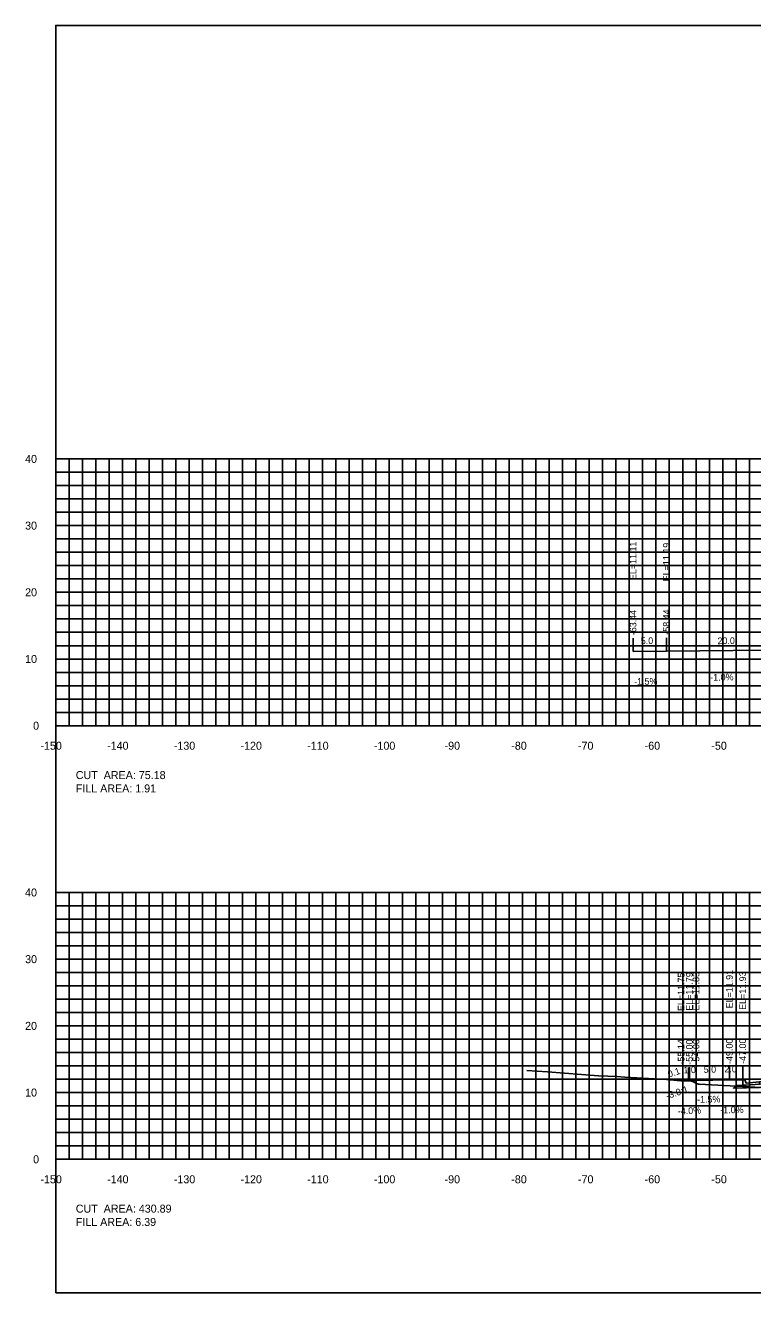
# Model space of a CAD drawing. Extents: x 1797682 to 1802785, y 249453 to 250269.
# Drawn here: x 1802476.4 to 1802585.5, y 250079.4 to 250269.4 of the extents above; entities that cross this region are included whole.
import ezdxf

# ---------------------------------------------------------------- set-up
doc = ezdxf.new("R2010")
doc.units = 0
for name, color, linetype in [('10', 7, 'Continuous'), ('3', 7, 'Continuous'), ('31', 7, 'Continuous'), ('4', 7, 'Continuous'), ('60', 7, 'Continuous'), ('ANNO-TXT', 7, 'Continuous'), ('BASE', 7, 'Continuous'), ('CL-CNST', 7, 'Continuous'), ('Level 62', 7, 'Continuous'), ('M-ROADS', 7, 'Continuous')]:
    doc.layers.add(name, color=color, linetype=linetype)

msp = doc.modelspace()

# ---------------------------------------------------------------- linework, layer by layer
for p, q in [((1802567.56, 250175.54), (1802567.56, 250177.54)), ((1802572.56, 250175.62), (1802572.56, 250177.62)), ((1802575.86, 250111.18), (1802575.86, 250113.18)), ((1802576, 250111.22), (1802576, 250113.22)), ((1802577, 250111.26), (1802577, 250113.26)), ((1802582, 250111.34), (1802582, 250113.34)), ((1802584, 250111.36), (1802584, 250113.36))]:
    msp.add_line(p, q)
for points in [[(1802481, 250079.43), (1802781, 250079.43), (1802781, 250269.43), (1802481, 250269.43)], [(1802586.5, 250111.02), (1802584.5, 250110.86), (1802584.33, 250111.36), (1802584, 250111.36), (1802584, 250110.52), (1802584.5, 250110.52), (1802586.5, 250110.68)]]:
    msp.add_lwpolyline(points, close=True)
at = {"layer": '60'}
for p, q in [((1802480.94, 250204.43), (1802481, 250204.43)), ((1802481, 250164.43), (1802481, 250204.43)), ((1802480.94, 250194.43), (1802481, 250194.43)), ((1802480.94, 250184.43), (1802481, 250184.43)), ((1802480.94, 250174.43), (1802481, 250174.43)), ((1802480.94, 250164.43), (1802481, 250164.43)), ((1802481, 250164.43), (1802781, 250164.43)), ((1802481, 250164.37), (1802481, 250164.43)), ((1802491, 250164.37), (1802491, 250164.43)), ((1802501, 250164.37), (1802501, 250164.43)), ((1802511, 250164.37), (1802511, 250164.43)), ((1802521, 250164.37), (1802521, 250164.43)), ((1802531, 250164.37), (1802531, 250164.43)), ((1802541, 250164.37), (1802541, 250164.43)), ((1802551, 250164.37), (1802551, 250164.43)), ((1802561, 250164.37), (1802561, 250164.43)), ((1802571, 250164.37), (1802571, 250164.43)), ((1802581, 250164.37), (1802581, 250164.43)), ((1802480.94, 250139.43), (1802481, 250139.43)), ((1802481, 250099.43), (1802481, 250139.43)), ((1802480.94, 250129.43), (1802481, 250129.43)), ((1802480.94, 250119.43), (1802481, 250119.43)), ((1802480.94, 250109.43), (1802481, 250109.43)), ((1802480.94, 250099.43), (1802481, 250099.43)), ((1802481, 250099.43), (1802781, 250099.43)), ((1802481, 250099.37), (1802481, 250099.43)), ((1802491, 250099.37), (1802491, 250099.43)), ((1802501, 250099.37), (1802501, 250099.43)), ((1802511, 250099.37), (1802511, 250099.43)), ((1802521, 250099.37), (1802521, 250099.43)), ((1802531, 250099.37), (1802531, 250099.43)), ((1802541, 250099.37), (1802541, 250099.43)), ((1802551, 250099.37), (1802551, 250099.43)), ((1802561, 250099.37), (1802561, 250099.43)), ((1802571, 250099.37), (1802571, 250099.43)), ((1802581, 250099.37), (1802581, 250099.43))]:
    msp.add_line(p, q, dxfattribs=at)
at = {"layer": 'BASE'}
msp.add_lwpolyline([(1802672.63, 250110.24), (1802676.53, 250110.16), (1802676.13, 250110.56), (1802675.13, 250110.58), (1802674.63, 250110.58), (1802672.63, 250110.74), (1802672.63, 250110.74), (1802631, 250111.66), (1802586.5, 250110.68), (1802586.5, 250110.68), (1802584.5, 250110.52), (1802584, 250110.52), (1802583, 250110.5), (1802582.6, 250110.09), (1802586.5, 250110.18), (1802631, 250111.16)], close=True, dxfattribs=at)
at = {"layer": 'CL-CNST'}
for points in [[(1802567.56, 250175.54), (1802572.56, 250175.62), (1802592.56, 250175.82), (1802592.89, 250175.82), (1802593.06, 250175.32), (1802595.06, 250175.48), (1802631, 250176.27), (1802640.34, 250176.06), (1802642.34, 250175.9), (1802642.51, 250176.4), (1802642.84, 250176.4), (1802672.7, 250176.7)], [(1802575.86, 250111.18), (1802576, 250111.22), (1802577, 250111.26), (1802582, 250111.34), (1802584, 250111.36), (1802584.33, 250111.36), (1802584.5, 250110.86), (1802586.5, 250111.02), (1802631, 250112), (1802672.63, 250111.08), (1802674.63, 250110.92), (1802674.8, 250111.42), (1802675.13, 250111.42), (1802689.23, 250111.56)]]:
    msp.add_lwpolyline(points, dxfattribs=at)
at = {"layer": 'Level 62'}
for p, q in [((1802481, 250204.43), (1802781, 250204.43)), ((1802481, 250164.43), (1802481, 250204.43)), ((1802483, 250164.43), (1802483, 250204.43)), ((1802485, 250164.43), (1802485, 250204.43)), ((1802487, 250164.43), (1802487, 250204.43)), ((1802489, 250164.43), (1802489, 250204.43)), ((1802491, 250164.43), (1802491, 250204.43)), ((1802493, 250164.43), (1802493, 250204.43)), ((1802495, 250164.43), (1802495, 250204.43)), ((1802497, 250164.43), (1802497, 250204.43)), ((1802499, 250164.43), (1802499, 250204.43)), ((1802501, 250164.43), (1802501, 250204.43)), ((1802503, 250164.43), (1802503, 250204.43)), ((1802505, 250164.43), (1802505, 250204.43)), ((1802507, 250164.43), (1802507, 250204.43)), ((1802509, 250164.43), (1802509, 250204.43)), ((1802511, 250164.43), (1802511, 250204.43)), ((1802513, 250164.43), (1802513, 250204.43)), ((1802515, 250164.43), (1802515, 250204.43)), ((1802517, 250164.43), (1802517, 250204.43)), ((1802519, 250164.43), (1802519, 250204.43)), ((1802521, 250164.43), (1802521, 250204.43)), ((1802523, 250164.43), (1802523, 250204.43)), ((1802525, 250164.43), (1802525, 250204.43)), ((1802527, 250164.43), (1802527, 250204.43)), ((1802529, 250164.43), (1802529, 250204.43)), ((1802531, 250164.43), (1802531, 250204.43)), ((1802533, 250164.43), (1802533, 250204.43)), ((1802535, 250164.43), (1802535, 250204.43)), ((1802537, 250164.43), (1802537, 250204.43)), ((1802539, 250164.43), (1802539, 250204.43)), ((1802541, 250164.43), (1802541, 250204.43)), ((1802543, 250164.43), (1802543, 250204.43)), ((1802545, 250164.43), (1802545, 250204.43)), ((1802547, 250164.43), (1802547, 250204.43)), ((1802549, 250164.43), (1802549, 250204.43)), ((1802551, 250164.43), (1802551, 250204.43)), ((1802553, 250164.43), (1802553, 250204.43)), ((1802555, 250164.43), (1802555, 250204.43)), ((1802557, 250164.43), (1802557, 250204.43)), ((1802559, 250164.43), (1802559, 250204.43)), ((1802561, 250164.43), (1802561, 250204.43)), ((1802563, 250164.43), (1802563, 250204.43)), ((1802565, 250164.43), (1802565, 250204.43)), ((1802567, 250164.43), (1802567, 250204.43)), ((1802569, 250164.43), (1802569, 250204.43)), ((1802571, 250164.43), (1802571, 250204.43)), ((1802573, 250164.43), (1802573, 250204.43)), ((1802575, 250164.43), (1802575, 250204.43)), ((1802577, 250164.43), (1802577, 250204.43)), ((1802579, 250164.43), (1802579, 250204.43)), ((1802581, 250164.43), (1802581, 250204.43)), ((1802583, 250164.43), (1802583, 250204.43)), ((1802585, 250164.43), (1802585, 250204.43)), ((1802481, 250202.43), (1802781, 250202.43)), ((1802481, 250200.43), (1802781, 250200.43)), ((1802481, 250198.43), (1802781, 250198.43)), ((1802481, 250196.43), (1802781, 250196.43)), ((1802481, 250194.43), (1802781, 250194.43)), ((1802481, 250192.43), (1802781, 250192.43)), ((1802481, 250190.43), (1802781, 250190.43)), ((1802481, 250188.43), (1802781, 250188.43)), ((1802481, 250186.43), (1802781, 250186.43)), ((1802481, 250184.43), (1802781, 250184.43)), ((1802481, 250182.43), (1802781, 250182.43)), ((1802481, 250180.43), (1802781, 250180.43)), ((1802481, 250178.43), (1802781, 250178.43)), ((1802481, 250176.43), (1802781, 250176.43)), ((1802481, 250174.43), (1802781, 250174.43)), ((1802481, 250172.43), (1802781, 250172.43)), ((1802481, 250170.43), (1802781, 250170.43)), ((1802481, 250168.43), (1802781, 250168.43)), ((1802481, 250166.43), (1802781, 250166.43)), ((1802481, 250164.43), (1802781, 250164.43)), ((1802481, 250139.43), (1802781, 250139.43)), ((1802481, 250099.43), (1802481, 250139.43)), ((1802483, 250099.43), (1802483, 250139.43)), ((1802485, 250099.43), (1802485, 250139.43)), ((1802487, 250099.43), (1802487, 250139.43)), ((1802489, 250099.43), (1802489, 250139.43)), ((1802491, 250099.43), (1802491, 250139.43)), ((1802493, 250099.43), (1802493, 250139.43)), ((1802495, 250099.43), (1802495, 250139.43)), ((1802497, 250099.43), (1802497, 250139.43)), ((1802499, 250099.43), (1802499, 250139.43)), ((1802501, 250099.43), (1802501, 250139.43)), ((1802503, 250099.43), (1802503, 250139.43)), ((1802505, 250099.43), (1802505, 250139.43)), ((1802507, 250099.43), (1802507, 250139.43)), ((1802509, 250099.43), (1802509, 250139.43)), ((1802511, 250099.43), (1802511, 250139.43)), ((1802513, 250099.43), (1802513, 250139.43)), ((1802515, 250099.43), (1802515, 250139.43)), ((1802517, 250099.43), (1802517, 250139.43)), ((1802519, 250099.43), (1802519, 250139.43)), ((1802521, 250099.43), (1802521, 250139.43)), ((1802523, 250099.43), (1802523, 250139.43)), ((1802525, 250099.43), (1802525, 250139.43)), ((1802527, 250099.43), (1802527, 250139.43)), ((1802529, 250099.43), (1802529, 250139.43)), ((1802531, 250099.43), (1802531, 250139.43)), ((1802533, 250099.43), (1802533, 250139.43)), ((1802535, 250099.43), (1802535, 250139.43)), ((1802537, 250099.43), (1802537, 250139.43)), ((1802539, 250099.43), (1802539, 250139.43)), ((1802541, 250099.43), (1802541, 250139.43)), ((1802543, 250099.43), (1802543, 250139.43)), ((1802545, 250099.43), (1802545, 250139.43)), ((1802547, 250099.43), (1802547, 250139.43)), ((1802549, 250099.43), (1802549, 250139.43)), ((1802551, 250099.43), (1802551, 250139.43)), ((1802553, 250099.43), (1802553, 250139.43)), ((1802555, 250099.43), (1802555, 250139.43)), ((1802557, 250099.43), (1802557, 250139.43)), ((1802559, 250099.43), (1802559, 250139.43)), ((1802561, 250099.43), (1802561, 250139.43)), ((1802563, 250099.43), (1802563, 250139.43)), ((1802565, 250099.43), (1802565, 250139.43)), ((1802567, 250099.43), (1802567, 250139.43)), ((1802569, 250099.43), (1802569, 250139.43)), ((1802571, 250099.43), (1802571, 250139.43)), ((1802573, 250099.43), (1802573, 250139.43)), ((1802575, 250099.43), (1802575, 250139.43)), ((1802577, 250099.43), (1802577, 250139.43)), ((1802579, 250099.43), (1802579, 250139.43)), ((1802581, 250099.43), (1802581, 250139.43)), ((1802583, 250099.43), (1802583, 250139.43)), ((1802585, 250099.43), (1802585, 250139.43)), ((1802481, 250137.43), (1802781, 250137.43)), ((1802481, 250135.43), (1802781, 250135.43)), ((1802481, 250133.43), (1802781, 250133.43)), ((1802481, 250131.43), (1802781, 250131.43)), ((1802481, 250129.43), (1802781, 250129.43)), ((1802481, 250127.43), (1802781, 250127.43)), ((1802481, 250125.43), (1802781, 250125.43)), ((1802481, 250123.43), (1802781, 250123.43)), ((1802481, 250121.43), (1802781, 250121.43)), ((1802481, 250119.43), (1802781, 250119.43)), ((1802481, 250117.43), (1802781, 250117.43)), ((1802481, 250115.43), (1802781, 250115.43)), ((1802481, 250113.43), (1802781, 250113.43)), ((1802481, 250111.43), (1802781, 250111.43)), ((1802481, 250109.43), (1802781, 250109.43)), ((1802481, 250107.43), (1802781, 250107.43)), ((1802481, 250105.43), (1802781, 250105.43)), ((1802481, 250103.43), (1802781, 250103.43)), ((1802481, 250101.43), (1802781, 250101.43)), ((1802481, 250099.43), (1802781, 250099.43))]:
    msp.add_line(p, q, dxfattribs=at)
at = {"layer": 'M-ROADS'}
msp.add_lwpolyline([(1802551.65, 250112.75), (1802554.74, 250112.54), (1802562.4, 250111.94), (1802565.16, 250111.83), (1802566.33, 250111.75), (1802572.56, 250111.39), (1802574.7, 250111.21), (1802576.17, 250111.17), (1802576.49, 250111.08), (1802576.61, 250111.05), (1802576.68, 250111.02), (1802576.89, 250110.9), (1802576.91, 250110.91), (1802577.15, 250110.73), (1802577.16, 250110.73), (1802577.18, 250110.73), (1802577.2, 250110.69), (1802577.24, 250110.72), (1802577.37, 250110.71), (1802577.48, 250110.69), (1802587.68, 250110.14)], dxfattribs=at)

# ---------------------------------------------------------------- texts
msp.add_text('-3.0:1', height=1, rotation=18.4349).set_placement((1802572.68, 250108.43))
at = {"layer": '10'}
for s, p in [('-150', (1802478.7, 250160.83)), ('-140', (1802488.7, 250160.83)), ('-130', (1802498.7, 250160.83)), ('-120', (1802508.7, 250160.83)), ('-110', (1802518.7, 250160.83)), ('-100', (1802528.7, 250160.83)), ('-90', (1802539.3, 250160.83)), ('-80', (1802549.3, 250160.83)), ('-70', (1802559.3, 250160.83)), ('-60', (1802569.3, 250160.83)), ('-50', (1802579.3, 250160.83)), ('-150', (1802478.7, 250095.83)), ('-140', (1802488.7, 250095.83)), ('-130', (1802498.7, 250095.83)), ('-120', (1802508.7, 250095.83)), ('-110', (1802518.7, 250095.83)), ('-100', (1802528.7, 250095.83)), ('-90', (1802539.3, 250095.83)), ('-80', (1802549.3, 250095.83)), ('-70', (1802559.3, 250095.83)), ('-60', (1802569.3, 250095.83)), ('-50', (1802579.3, 250095.83))]:
    msp.add_text(s, height=1.2, dxfattribs=at).set_placement(p)
at = {"layer": '3'}
for s, p in [('EL=11.11', (1802568.06, 250186.27)), ('EL=11.19', (1802573.06, 250186.09)), ('-63.44', (1802568.06, 250178)), ('-58.44', (1802573.06, 250178.08)), ('EL=11.83', (1802577.5, 250121.74)), ('EL=11.91', (1802582.5, 250122.06)), ('EL=11.93', (1802584.5, 250121.83)), ('EL=11.75', (1802575.27, 250121.65)), ('EL=11.79', (1802576.5, 250121.7)), ('-55.14', (1802575.27, 250113.63)), ('-55.00', (1802576.5, 250113.6)), ('-54.00', (1802577.5, 250113.64)), ('-49.00', (1802582.5, 250113.72)), ('-47.00', (1802584.5, 250113.74))]:
    msp.add_text(s, height=1, rotation=90, dxfattribs=at).set_placement(p)
at = {"layer": '31'}
for s, p in [('40', (1802476.4, 250203.83)), ('30', (1802476.4, 250193.83)), ('20', (1802476.4, 250183.83)), ('10', (1802476.4, 250173.83)), ('0', (1802477.6, 250163.83)), ('40', (1802476.4, 250138.83)), ('30', (1802476.4, 250128.83)), ('20', (1802476.4, 250118.83)), ('10', (1802476.4, 250108.83)), ('0', (1802477.6, 250098.83))]:
    msp.add_text(s, height=1.2, dxfattribs=at).set_placement(p)
at = {"layer": '4'}
for s, rotation, p in [('5.0', 0.8594, (1802568.73, 250176.66)), ('20.0', 0.8594, (1802580.23, 250176.65)), ('-1.5%', 0.8594, (1802567.73, 250170.55)), ('-1.0%', 0.8594, (1802579.14, 250171.18)), ('0.1', 18.4349, (1802572.95, 250111.68)), ('1.0', 2.2906, (1802575.14, 250112.29)), ('5.0', 0.8594, (1802578.16, 250112.38)), ('2.0', 0.5729, (1802581.26, 250112.44)), ('-1.5%', 0.8594, (1802577.17, 250107.9)), ('-4.0%', 2.2906, (1802574.29, 250106.15)), ('-1.0%', 0.5729, (1802580.64, 250106.32))]:
    msp.add_text(s, height=1, rotation=rotation, dxfattribs=at).set_placement(p)
at = {"layer": '60'}
for p in [(1802481, 250164.43), (1802481, 250099.43)]:
    msp.add_text('-', height=0.0001, dxfattribs=at).set_placement(p)
at = {"layer": 'ANNO-TXT'}
for s, p in [('CUT  AREA: 75.18', (1802484, 250156.43)), ('FILL AREA: 1.91', (1802484, 250154.43)), ('CUT  AREA: 430.89', (1802484, 250091.43)), ('FILL AREA: 6.39', (1802484, 250089.43))]:
    msp.add_text(s, height=1.2, dxfattribs=at).set_placement(p)

doc.saveas('drawing.dxf')
